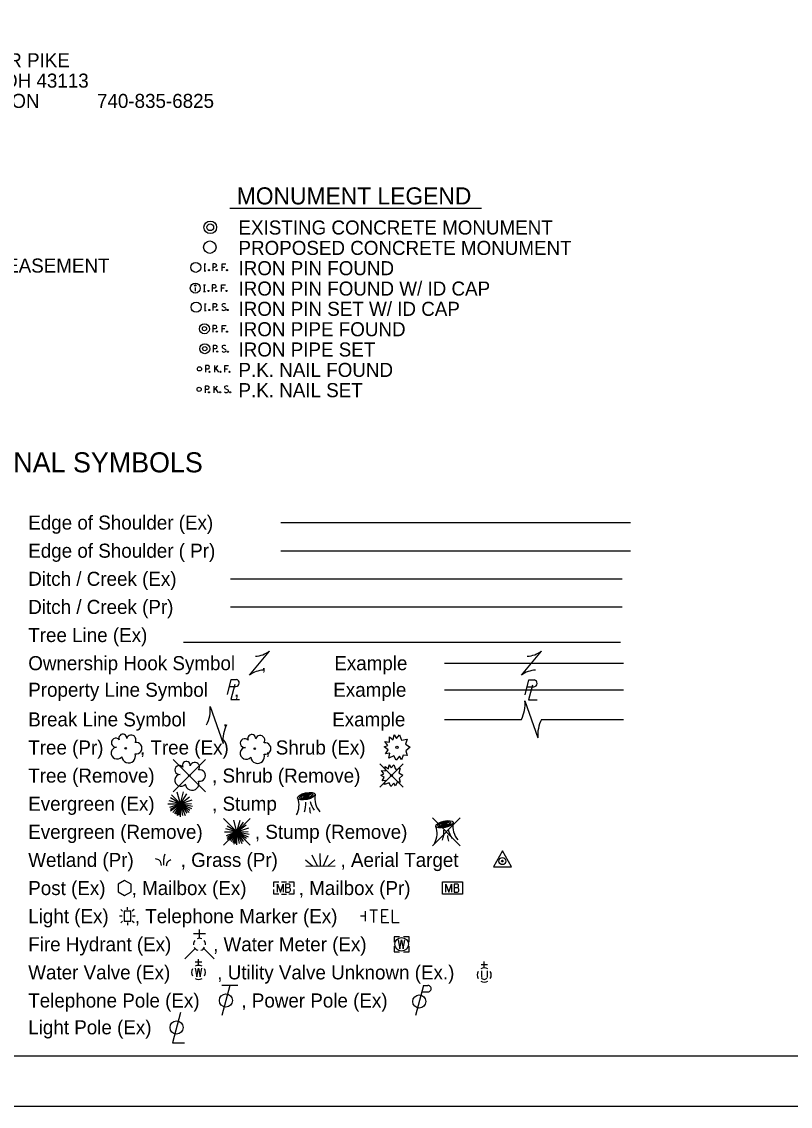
# Model space of a CAD drawing. Extents: x 0 to 34, y 0 to 22.
# Drawn here: x 7.92 to 15.57, y 0 to 10.8 of the extents above; entities that cross this region are included whole.
import ezdxf

# ---------------------------------------------------------------- set-up
doc = ezdxf.new("R2010")
doc.units = 0
for name, color, linetype in [('SH_Border', 7, 'Continuous'), ('SH_Cut_Line', 7, 'Continuous'), ('SH_Text', 7, 'Continuous')]:
    doc.layers.add(name, color=color, linetype=linetype)

msp = doc.modelspace()

# ---------------------------------------------------------------- linework, layer by layer
at = {"layer": 'SH_Border'}
msp.add_lwpolyline([(1.5, 21.5), (33.5, 21.5), (33.5, 0.5), (1.5, 0.5)], close=True, dxfattribs=at)
at = {"layer": 'SH_Cut_Line'}
msp.add_lwpolyline([(0, 0), (34, 0), (34, 22), (0, 22)], close=True, dxfattribs=at)
at = {"layer": 'SH_Text'}
for p, q in [((9.99, 8.945), (12.497, 8.945)), ((9.734, 8.39), (9.75, 8.39)), ((9.734, 8.39), (9.75, 8.39)), ((9.734, 8.323), (9.75, 8.323)), ((9.742, 8.323), (9.742, 8.39)), ((9.819, 8.358), (9.845, 8.358)), ((9.912, 8.323), (9.912, 8.39)), ((9.912, 8.39), (9.951, 8.39)), ((9.912, 8.357), (9.94, 8.357)), ((9.646, 8.155), (9.646, 8.118)), ((9.729, 8.183), (9.746, 8.183)), ((9.729, 8.183), (9.746, 8.183)), ((9.729, 8.117), (9.746, 8.117)), ((9.738, 8.117), (9.738, 8.183)), ((9.814, 8.151), (9.841, 8.151)), ((9.908, 8.117), (9.908, 8.183)), ((9.908, 8.183), (9.946, 8.183)), ((9.908, 8.151), (9.935, 8.151)), ((9.737, 7.994), (9.754, 7.994)), ((9.737, 7.994), (9.754, 7.994)), ((9.737, 7.927), (9.754, 7.927)), ((9.745, 7.927), (9.745, 7.994)), ((9.822, 7.962), (9.849, 7.962)), ((9.916, 7.97), (9.947, 7.954)), ((9.914, 7.712), (9.914, 7.778)), ((9.914, 7.778), (9.952, 7.778)), ((9.82, 7.746), (9.847, 7.746)), ((9.914, 7.746), (9.941, 7.746)), ((9.823, 7.547), (9.85, 7.547)), ((9.917, 7.555), (9.948, 7.539)), ((9.747, 7.346), (9.774, 7.346)), ((9.84, 7.312), (9.84, 7.378)), ((9.84, 7.336), (9.872, 7.378)), ((9.851, 7.35), (9.878, 7.312)), ((9.939, 7.312), (9.939, 7.378)), ((9.939, 7.378), (9.977, 7.378)), ((9.939, 7.346), (9.966, 7.346)), ((9.743, 7.142), (9.769, 7.142)), ((9.835, 7.108), (9.835, 7.174)), ((9.835, 7.132), (9.867, 7.174)), ((9.846, 7.146), (9.873, 7.108)), ((9.941, 7.151), (9.972, 7.135)), ((10.498, 5.814), (13.982, 5.814)), ((10.498, 5.534), (13.982, 5.534)), ((9.998, 5.254), (13.898, 5.254)), ((9.998, 4.974), (13.898, 4.974)), ((9.53, 4.624), (13.88, 4.624)), ((10.185, 4.294), (10.385, 4.534)), ((12.894, 4.294), (13.094, 4.534)), ((10.285, 4.414), (10.285, 4.414)), ((12.128, 4.414), (13.91, 4.414)), ((12.994, 4.414), (12.994, 4.414)), ((9.986, 4.183), (10.05, 4.183)), ((10.026, 4.152), (10.026, 4.152)), ((12.128, 4.149), (13.91, 4.149)), ((12.951, 4.179), (13.016, 4.179)), ((12.991, 4.148), (12.991, 4.148)), ((12.929, 4.038), (13.059, 3.67)), ((9.793, 3.982), (9.923, 3.614)), ((9.858, 3.798), (9.858, 3.798)), ((12.128, 3.854), (12.894, 3.854)), ((12.994, 3.854), (12.994, 3.854)), ((13.093, 3.854), (13.91, 3.854)), ((9.426, 3.454), (9.747, 3.133)), ((9.747, 3.454), (9.426, 3.133)), ((11.485, 3.41), (11.717, 3.178)), ((11.717, 3.41), (11.485, 3.178)), ((9.586, 3.294), (9.586, 3.294)), ((11.601, 3.294), (11.601, 3.294)), ((9.497, 3.014), (9.386, 3.043)), ((9.497, 3.014), (9.399, 3.071)), ((9.497, 3.014), (9.409, 3.101)), ((9.497, 3.014), (9.466, 3.129)), ((9.497, 3.014), (9.528, 3.131)), ((9.497, 3.014), (9.563, 3.111)), ((9.497, 3.014), (9.588, 3.084)), ((9.497, 3.014), (9.615, 3.054)), ((9.373, 3.014), (9.497, 3.014)), ((9.497, 3.014), (9.389, 2.975)), ((9.497, 3.014), (9.397, 2.957)), ((9.497, 3.014), (9.399, 2.939)), ((9.497, 3.014), (9.423, 2.927)), ((9.497, 3.014), (9.439, 2.913)), ((9.497, 3.014), (9.455, 2.905)), ((9.497, 3.014), (9.465, 2.892)), ((9.497, 3.014), (9.483, 2.899)), ((9.497, 3.014), (9.609, 3.016)), ((9.497, 2.883), (9.497, 3.014)), ((9.497, 3.014), (9.52, 2.898)), ((9.497, 3.014), (9.545, 2.897)), ((9.497, 3.014), (9.56, 2.919)), ((9.497, 3.014), (9.586, 2.926)), ((9.497, 3.014), (9.592, 2.95)), ((9.497, 3.014), (9.608, 2.965)), ((9.497, 3.014), (9.617, 2.99)), ((10.77, 3.014), (10.77, 3.014)), ((9.927, 2.867), (10.194, 2.6)), ((10.194, 2.867), (9.927, 2.6)), ((10.061, 2.734), (9.973, 2.821)), ((10.061, 2.734), (10.03, 2.849)), ((10.061, 2.734), (10.092, 2.851)), ((10.061, 2.734), (10.127, 2.831)), ((12.007, 2.873), (12.285, 2.595)), ((12.285, 2.873), (12.007, 2.595)), ((9.937, 2.734), (10.061, 2.734)), ((10.061, 2.734), (9.95, 2.763)), ((10.061, 2.734), (9.953, 2.695)), ((10.061, 2.734), (9.961, 2.677)), ((10.061, 2.734), (9.963, 2.791)), ((10.061, 2.734), (9.963, 2.659)), ((10.061, 2.734), (9.987, 2.647)), ((10.061, 2.734), (10.003, 2.633)), ((10.061, 2.734), (10.019, 2.625)), ((10.061, 2.734), (10.029, 2.612)), ((10.061, 2.734), (10.047, 2.619)), ((10.061, 2.734), (10.152, 2.804)), ((10.061, 2.734), (10.179, 2.774)), ((10.061, 2.734), (10.173, 2.736)), ((10.061, 2.603), (10.061, 2.734)), ((10.061, 2.734), (10.084, 2.618)), ((10.061, 2.734), (10.109, 2.617)), ((10.061, 2.734), (10.124, 2.639)), ((10.061, 2.734), (10.15, 2.646)), ((10.061, 2.734), (10.156, 2.67)), ((10.061, 2.734), (10.172, 2.685)), ((10.061, 2.734), (10.181, 2.71)), ((10.061, 2.734), (10.061, 2.734)), ((12.146, 2.734), (12.146, 2.734)), ((12.146, 2.734), (12.146, 2.734)), ((10.862, 2.393), (10.81, 2.5)), ((10.892, 2.394), (10.89, 2.519)), ((10.922, 2.394), (10.971, 2.502)), ((10.814, 2.393), (10.745, 2.45)), ((10.746, 2.392), (11.038, 2.396)), ((10.971, 2.395), (11.037, 2.454)), ((10.503, 2.235), (10.553, 2.235)), ((10.529, 2.174), (10.529, 2.174)), ((12.207, 2.174), (12.207, 2.174)), ((10.503, 2.113), (10.553, 2.113)), ((8.921, 1.942), (8.903, 1.961)), ((8.969, 1.958), (8.969, 1.984)), ((9.036, 1.961), (9.017, 1.942)), ((8.917, 1.894), (8.891, 1.894)), ((8.921, 1.845), (8.903, 1.827)), ((8.969, 1.894), (8.969, 1.894)), ((9.036, 1.827), (9.017, 1.845)), ((9.048, 1.894), (9.021, 1.894)), ((11.342, 1.894), (11.292, 1.894)), ((11.342, 1.844), (11.342, 1.944)), ((8.969, 1.83), (8.969, 1.803)), ((9.687, 1.674), (9.687, 1.76)), ((9.747, 1.717), (9.627, 1.717)), ((9.645, 1.571), (9.541, 1.468)), ((9.687, 1.614), (9.687, 1.614)), ((9.687, 1.614), (9.687, 1.614)), ((9.73, 1.571), (9.834, 1.468)), ((11.701, 1.614), (11.701, 1.614)), ((9.71, 1.436), (9.646, 1.436)), ((9.678, 1.404), (9.678, 1.467)), ((12.556, 1.409), (12.493, 1.409)), ((12.524, 1.377), (12.524, 1.441)), ((9.678, 1.334), (9.678, 1.334)), ((12.497, 1.351), (12.497, 1.282)), ((12.524, 1.307), (12.524, 1.307)), ((12.552, 1.351), (12.552, 1.282)), ((10.071, 1.204), (9.911, 1.204)), ((9.991, 1.204), (9.911, 0.904)), ((11.92, 1.204), (11.84, 0.904)), ((11.92, 1.204), (11.963, 1.204)), ((11.903, 1.14), (11.963, 1.14))]:
    msp.add_line(p, q, dxfattribs=at)
for points in [[(9.845, 8.39), (9.819, 8.39), (9.819, 8.323)], [(9.841, 8.183), (9.814, 8.183), (9.814, 8.117)], [(9.849, 7.994), (9.822, 7.994), (9.822, 7.927)], [(9.847, 7.778), (9.82, 7.778), (9.82, 7.712)], [(9.85, 7.579), (9.823, 7.579), (9.823, 7.512)], [(9.774, 7.378), (9.747, 7.378), (9.747, 7.312)], [(9.769, 7.174), (9.743, 7.174), (9.743, 7.108)], [(9.965, 4.103), (10.004, 4.252), (10.055, 4.251)], [(12.93, 4.099), (12.969, 4.247), (13.021, 4.247)], [(10.039, 4.2), (9.999, 4.052), (10.087, 4.052)], [(13.005, 4.196), (12.965, 4.048), (13.052, 4.048)], [(11.649, 3.664), (11.68, 3.701), (11.7, 3.648), (11.755, 3.657), (11.738, 3.607), (11.785, 3.577), (11.743, 3.54), (11.755, 3.495), (11.717, 3.498), (11.701, 3.452), (11.68, 3.487), (11.646, 3.446), (11.624, 3.491), (11.573, 3.469), (11.583, 3.516), (11.542, 3.512), (11.566, 3.551), (11.528, 3.58), (11.565, 3.593), (11.534, 3.633), (11.581, 3.628), (11.579, 3.68), (11.617, 3.651), (11.627, 3.7), (11.649, 3.664)], [(11.597, 3.371), (11.623, 3.402), (11.64, 3.357), (11.687, 3.365), (11.672, 3.322), (11.713, 3.297), (11.676, 3.265), (11.687, 3.227), (11.655, 3.229), (11.641, 3.191), (11.623, 3.22), (11.594, 3.185), (11.576, 3.223), (11.532, 3.205), (11.541, 3.245), (11.506, 3.241), (11.526, 3.275), (11.494, 3.299), (11.525, 3.31), (11.499, 3.344), (11.539, 3.34), (11.537, 3.384), (11.569, 3.36), (11.578, 3.401), (11.597, 3.371)], [(8.876, 2.136), (8.941, 2.099), (9.006, 2.136), (9.006, 2.211), (8.941, 2.249), (8.876, 2.211), (8.876, 2.136)], [(10.429, 2.186), (10.429, 2.235), (10.477, 2.235)], [(10.477, 2.113), (10.429, 2.113), (10.429, 2.161)], [(10.464, 2.134), (10.464, 2.214), (10.493, 2.134), (10.521, 2.214), (10.521, 2.134)], [(10.58, 2.177), (10.583, 2.18), (10.585, 2.182), (10.586, 2.184), (10.587, 2.186), (10.588, 2.188), (10.589, 2.19), (10.59, 2.194), (10.59, 2.196), (10.59, 2.199), (10.59, 2.203), (10.588, 2.206), (10.586, 2.208), (10.583, 2.211), (10.581, 2.212), (10.579, 2.213), (10.576, 2.214), (10.545, 2.214), (10.545, 2.134), (10.58, 2.134), (10.584, 2.136), (10.588, 2.14), (10.591, 2.145), (10.593, 2.15), (10.594, 2.156), (10.594, 2.16), (10.593, 2.163), (10.59, 2.169), (10.587, 2.173), (10.58, 2.177), (10.545, 2.177)], [(10.579, 2.235), (10.629, 2.235), (10.629, 2.186)], [(10.629, 2.161), (10.629, 2.113), (10.579, 2.113)], [(12.142, 2.134), (12.142, 2.214), (12.171, 2.134), (12.199, 2.214), (12.199, 2.134)], [(12.258, 2.177), (12.261, 2.18), (12.263, 2.182), (12.264, 2.184), (12.265, 2.186), (12.266, 2.188), (12.267, 2.19), (12.268, 2.194), (12.268, 2.196), (12.268, 2.199), (12.268, 2.203), (12.266, 2.206), (12.264, 2.208), (12.261, 2.211), (12.259, 2.212), (12.258, 2.213), (12.254, 2.214), (12.224, 2.214), (12.224, 2.134), (12.258, 2.134), (12.263, 2.136), (12.266, 2.14), (12.27, 2.145), (12.271, 2.15), (12.272, 2.156), (12.272, 2.16), (12.271, 2.163), (12.268, 2.169), (12.265, 2.173), (12.258, 2.177), (12.224, 2.177)], [(11.383, 1.956), (11.461, 1.956)], [(11.422, 1.956), (11.422, 1.831)], [(11.568, 1.956), (11.5, 1.956), (11.5, 1.831), (11.573, 1.831)], [(11.607, 1.956), (11.607, 1.831), (11.675, 1.831)], [(11.5, 1.894), (11.548, 1.894)], [(11.681, 1.689), (11.626, 1.689), (11.626, 1.634)], [(11.668, 1.659), (11.684, 1.569), (11.701, 1.659), (11.718, 1.569), (11.734, 1.659)], [(11.776, 1.634), (11.776, 1.689), (11.721, 1.689)], [(11.626, 1.594), (11.626, 1.539), (11.681, 1.539)], [(11.721, 1.539), (11.776, 1.539), (11.776, 1.594)], [(9.646, 1.375), (9.662, 1.289), (9.678, 1.375), (9.694, 1.289), (9.71, 1.375)], [(9.499, 0.933), (9.42, 0.633), (9.538, 0.633)]]:
    msp.add_lwpolyline(points, dxfattribs=at)
for points in [[(12.615, 2.384), (12.795, 2.384), (12.705, 2.545)], [(12.107, 2.235), (12.307, 2.235), (12.307, 2.113), (12.107, 2.113)], [(8.936, 1.844), (9.003, 1.844), (9.003, 1.944), (8.936, 1.944)]]:
    msp.add_lwpolyline(points, close=True, dxfattribs=at)
for centre, radius in [((9.795, 8.755), 0.0625), ((9.795, 8.755), 0.0333), ((9.791, 8.557), 0.0625), ((9.65, 8.356), 0.05), ((9.782, 8.328), 0.00583), ((9.859, 8.328), 0.00583), ((9.961, 8.328), 0.00583), ((9.646, 8.15), 0.05), ((9.646, 8.177), 0.00667), ((9.778, 8.121), 0.00583), ((9.855, 8.121), 0.00583), ((9.956, 8.121), 0.00583), ((9.654, 7.96), 0.05), ((9.785, 7.932), 0.00583), ((9.862, 7.932), 0.00583), ((9.969, 7.931), 0.00583), ((9.737, 7.745), 0.05), ((9.737, 7.745), 0.0206), ((9.86, 7.716), 0.00583), ((9.962, 7.716), 0.00583), ((9.74, 7.546), 0.05), ((9.74, 7.546), 0.0208), ((9.863, 7.517), 0.00583), ((9.97, 7.516), 0.00583), ((9.687, 7.345), 0.0207), ((9.787, 7.316), 0.00583), ((9.897, 7.316), 0.00583), ((9.987, 7.316), 0.00583), ((9.684, 7.141), 0.0206), ((9.783, 7.112), 0.00583), ((9.894, 7.112), 0.00583), ((9.994, 7.112), 0.00583), ((8.953, 3.566), 0.0084), ((10.238, 3.562), 0.0072), ((11.654, 3.574), 0.0115), ((9.586, 3.294), 0.0072), ((11.601, 3.294), 0.00979), ((12.705, 2.442), 0.035), ((12.705, 2.442), 0.008), ((11.701, 1.614), 0.0675), ((9.951, 1.054), 0.065), ((11.877, 1.044), 0.065), ((9.459, 0.785), 0.065)]:
    msp.add_circle(centre, radius, dxfattribs=at)
for centre, radius, start, end in [((9.843, 8.374), 0.0162, 278.8803, 81.1197), ((9.839, 8.167), 0.0162, 278.8803, 81.1197), ((9.846, 7.978), 0.0162, 278.8803, 81.1197), ((9.923, 7.98), 0.0118, 126.2587, 236.3675), ((9.931, 7.955), 0.0276, 223.6695, 304.3963), ((9.932, 7.959), 0.0349, 61.3463, 118.6537), ((9.937, 7.943), 0.0148, 311.4883, 47.9358), ((9.844, 7.762), 0.0162, 278.8803, 81.1197), ((9.847, 7.563), 0.0162, 278.8803, 81.1197), ((9.924, 7.565), 0.0118, 126.2587, 236.3675), ((9.934, 7.544), 0.0349, 61.3463, 118.6537), ((9.932, 7.54), 0.0276, 223.6695, 304.3963), ((9.938, 7.528), 0.0148, 311.4883, 47.9358), ((9.771, 7.362), 0.0162, 278.8803, 81.1197), ((9.767, 7.158), 0.0162, 278.8803, 81.1197), ((9.948, 7.161), 0.0118, 126.2587, 236.3675), ((9.957, 7.14), 0.0349, 61.3463, 118.6537), ((9.962, 7.124), 0.0148, 311.4883, 47.9358), ((9.956, 7.136), 0.0276, 223.6695, 304.3963), ((10.227, 4.749), 0.267, 273.6945, 306.337), ((12.935, 4.749), 0.267, 273.6945, 306.337), ((10.343, 4.079), 0.267, 93.6945, 126.337), ((13.052, 4.079), 0.267, 93.6945, 126.337), ((10.05, 4.217), 0.0345, 270.471, 81.3281), ((13.016, 4.213), 0.0345, 270.471, 81.3281), ((12.597, 4.006), 0.334, 332.9422, 5.5848), ((9.461, 3.95), 0.334, 332.9422, 5.5848), ((10.255, 3.647), 0.334, 152.9422, 185.5848), ((13.391, 3.702), 0.334, 152.9422, 185.5848), ((8.924, 3.667), 0.0395, 354.0047, 205.9741), ((9.008, 3.651), 0.0466, 323.83, 165.0376), ((10.208, 3.663), 0.0395, 354.0047, 205.9741), ((10.292, 3.647), 0.0466, 323.83, 165.0376), ((8.867, 3.519), 0.0592, 96.1722, 320.5737), ((8.854, 3.622), 0.0441, 39.0625, 279.5412), ((9.057, 3.567), 0.0574, 259.1453, 101.4596), ((10.152, 3.516), 0.0592, 96.1722, 320.5737), ((10.138, 3.618), 0.0441, 39.0625, 279.5412), ((10.342, 3.563), 0.0574, 259.1453, 101.4596), ((8.981, 3.488), 0.0685, 184.9476, 19.4572), ((10.266, 3.484), 0.0685, 184.9476, 19.4572), ((9.487, 3.35), 0.0441, 39.0625, 279.5412), ((9.557, 3.395), 0.0395, 354.0047, 205.9741), ((9.641, 3.379), 0.0466, 323.83, 165.0376), ((9.69, 3.295), 0.0574, 259.1453, 101.4596), ((9.501, 3.247), 0.0592, 96.1722, 320.5737), ((9.614, 3.216), 0.0685, 184.9476, 19.4572), ((10.479, 2.997), 0.2, 331.5338, 20.9269), ((10.494, 3.015), 0.253, 340.7938, 3.5481), ((11.096, 3.117), 0.316, 194.9653, 212.1216), ((11.051, 3.071), 0.215, 171.4106, 219.9194), ((10.966, 2.974), 0.182, 178.7926, 197.1224), ((12.426, 2.791), 0.215, 171.4106, 219.9194), ((11.854, 2.717), 0.2, 331.5338, 20.9269), ((11.87, 2.735), 0.253, 340.7938, 3.5481), ((12.471, 2.837), 0.316, 194.9653, 212.1216), ((12.341, 2.694), 0.182, 178.7926, 197.1224), ((9.687, 1.614), 0.06, 140.021, 184.0629), ((9.687, 1.614), 0.06, 68.1395, 112.038), ((9.687, 1.614), 0.06, 356.0165, 39.9889), ((9.687, 1.614), 0.06, 211.8788, 255.8479), ((9.687, 1.614), 0.06, 283.8239, 329.9097), ((9.678, 1.334), 0.07, 150.0184, 209.9816), ((9.678, 1.334), 0.07, 60.0184, 120.0157), ((9.678, 1.334), 0.07, 330.0184, 29.9816), ((12.524, 1.308), 0.07, 150.0184, 209.9816), ((12.524, 1.308), 0.07, 60.0184, 120.0157), ((12.524, 1.308), 0.07, 330.0184, 29.9816), ((9.678, 1.334), 0.07, 239.9843, 299.9816), ((11.963, 1.172), 0.0319, 268.8767, 91.1233), ((12.524, 1.308), 0.07, 239.9843, 299.9816), ((12.524, 1.294), 0.03, 205.1924, 334.8076)]:
    msp.add_arc(centre, radius, start, end, dxfattribs=at)
for centre, major_axis in [((10.752, 3.089), (0.0868, 0.0187)), ((10.752, 3.089), (0.0651, 0.0141)), ((10.752, 3.089), (0.0488, 0.0105)), ((10.752, 3.089), (0.0275, 0.0059)), ((10.752, 3.089), (0.0154, 0.0033)), ((12.127, 2.809), (0.0868, 0.0187)), ((12.127, 2.809), (0.0651, 0.0141)), ((12.127, 2.809), (0.0488, 0.0105)), ((12.127, 2.809), (0.0275, 0.0059)), ((12.127, 2.809), (0.0154, 0.0033))]:
    msp.add_ellipse(centre, major_axis=major_axis, ratio=0.36865, dxfattribs=at)
for points in [[(9.333, 2.402), (9.333, 2.45), (9.339, 2.494), (9.347, 2.515)], [(9.245, 2.469), (9.287, 2.452), (9.305, 2.398)], [(9.36, 2.395), (9.372, 2.434), (9.402, 2.457)]]:
    msp.add_spline(points, degree=3, dxfattribs=at)

# ---------------------------------------------------------------- texts
for s, height, p in [('500 LANCASTER PIKE', 0.14, (6.43, 10.349)), ('CIRCLEVILLE, OH 43113', 0.14, (6.43, 10.146)), ('TRAVIS BRANNON           740-835-6825', 0.14, (6.43, 9.944)), ('MONUMENT LEGEND', 0.17, (10.059, 8.983)), ('EXISTING CONCRETE MONUMENT', 0.14, (10.076, 8.683)), ('PROPOSED CONCRETE MONUMENT', 0.14, (10.076, 8.48)), ('SH = STANDARD HIGHWAY EASEMENT', 0.14, (5.26, 8.304)), ('IRON PIN FOUND', 0.14, (10.076, 8.278)), ('IRON PIN FOUND W/ ID CAP', 0.14, (10.076, 8.075)), ('IRON PIN SET W/ ID CAP', 0.14, (10.076, 7.873)), ('IRON PIPE FOUND', 0.14, (10.076, 7.67)), ('IRON PIPE SET', 0.14, (10.076, 7.468)), ('P.K. NAIL FOUND', 0.14, (10.076, 7.265)), ('P.K. NAIL SET', 0.14, (10.076, 7.063)), ('CONVENTIONAL SYMBOLS', 0.2, (6.243, 6.314)), ('Edge of Shoulder (Ex)', 0.14, (7.982, 5.744)), ('Edge of Shoulder ( Pr)', 0.14, (7.982, 5.464)), ('Ditch / Creek (Ex)', 0.14, (7.982, 5.184)), ('Ditch / Creek (Pr)', 0.14, (7.982, 4.904)), ('Tree Line (Ex)', 0.14, (7.982, 4.624)), ('Ownership Hook Symbol     ,             Example', 0.14, (7.982, 4.344)), ('Property Line Symbol     ,                  Example', 0.14, (7.982, 4.079)), ('Break Line Symbol       ,                    Example', 0.14, (7.982, 3.784)), ('Tree (Pr)       , Tree (Ex)       , Shrub (Ex)', 0.14, (7.982, 3.504)), ('Tree (Remove)           , Shrub (Remove)', 0.14, (7.982, 3.224)), ('Evergreen (Ex)           , Stump ', 0.14, (7.982, 2.944)), ('Evergreen (Remove)          , Stump (Remove)', 0.14, (7.982, 2.664)), ('Wetland (Pr)         , Grass (Pr)            , Aerial Target    ', 0.14, (7.982, 2.384)), ('Post (Ex)     , Mailbox (Ex)          , Mailbox (Pr)', 0.14, (7.982, 2.104)), ('Light (Ex)     , Telephone Marker (Ex)     ', 0.14, (7.982, 1.824)), ('Fire Hydrant (Ex)        , Water Meter (Ex)', 0.14, (7.982, 1.544)), ('Water Valve (Ex)         , Utility Valve Unknown (Ex.)', 0.14, (7.982, 1.264)), ('Telephone Pole (Ex)        , Power Pole (Ex)', 0.14, (7.982, 0.984)), ('Light Pole (Ex)     ', 0.14, (7.982, 0.717))]:
    msp.add_text(s, height=height, dxfattribs=at).set_placement(p)

doc.saveas('drawing.dxf')
